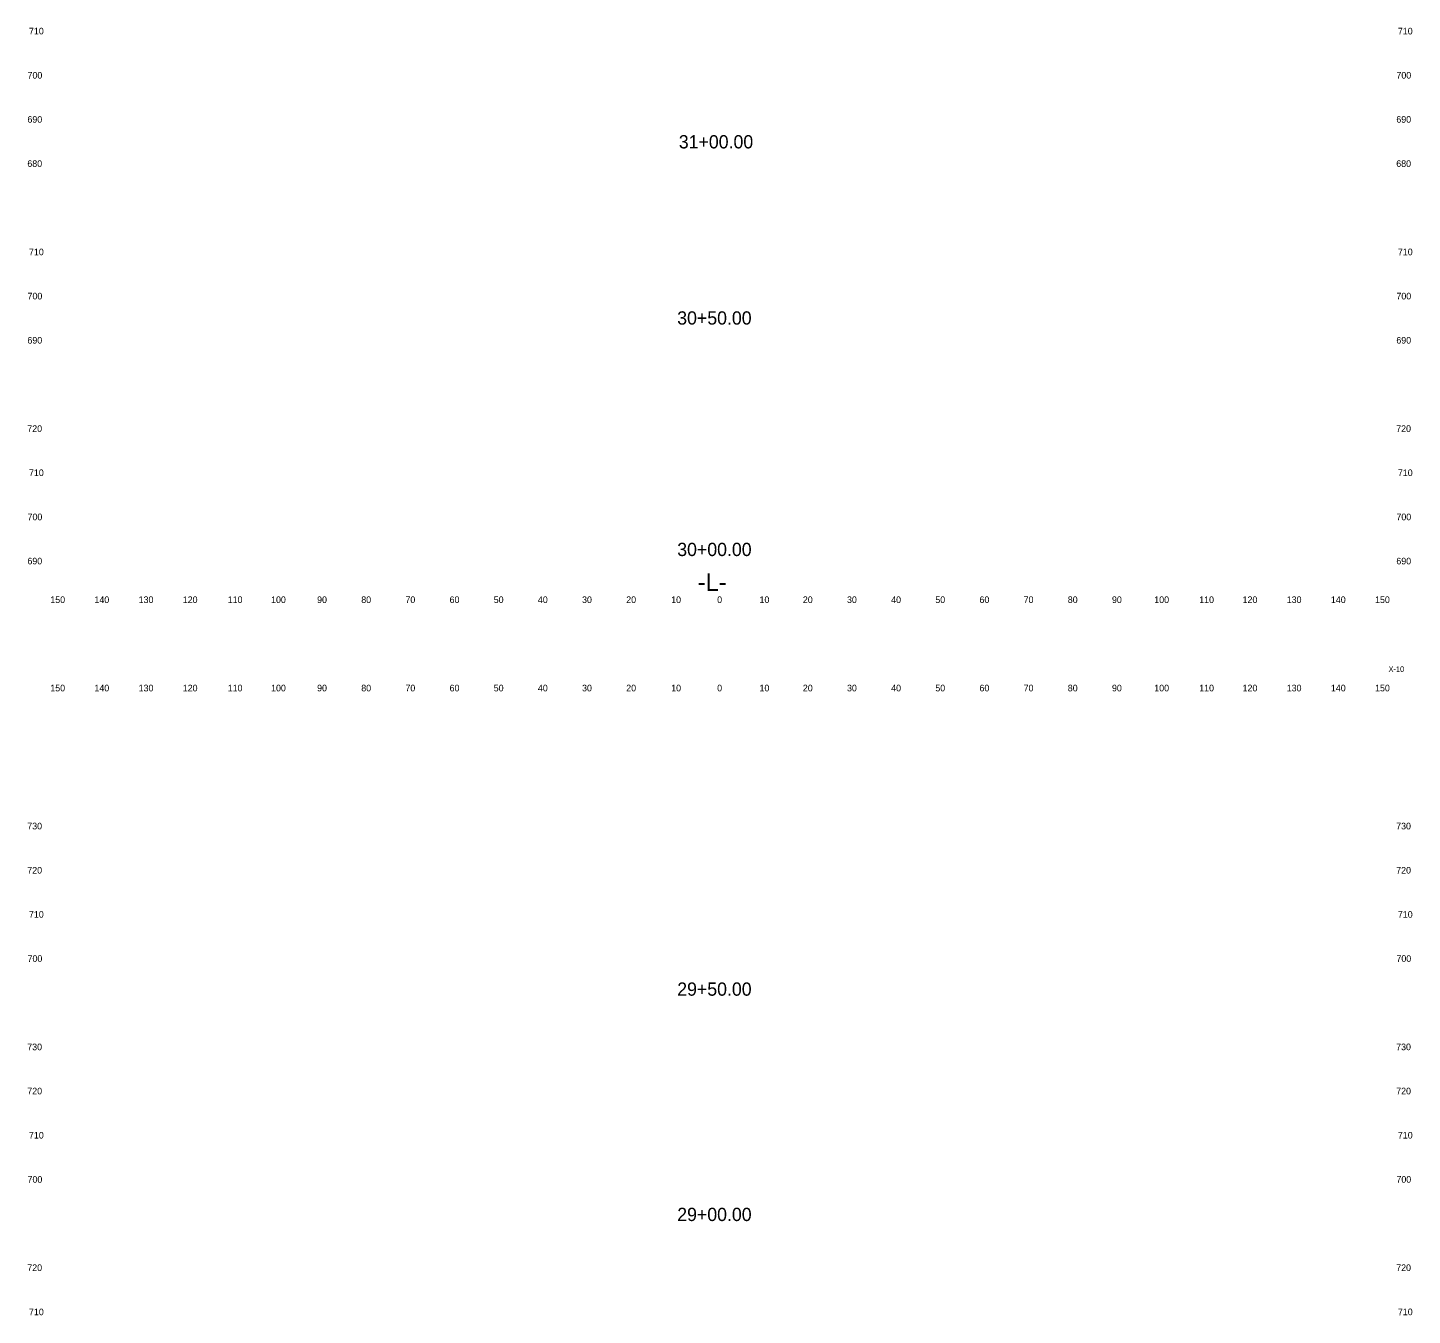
# Model space of a CAD drawing. Extents: x 3 to 317, y 0 to 2407.
# Drawn here: x 3.3 to 316.9, y 1820 to 2111.5 of the extents above; entities that cross this region are included whole.
import ezdxf

# ---------------------------------------------------------------- set-up
doc = ezdxf.new("R2010")
doc.units = 0
for name, color, linetype in [('Prop XS Ditch Standard Text', 7, 'Continuous'), ('Prop XS Dump Level', 7, 'Continuous'), ('Prop XS SE Text', 7, 'Continuous'), ('Prop XS Sheet Number', 7, 'Continuous'), ('Prop XS SS Elevation Text', 7, 'Continuous')]:
    doc.layers.add(name, color=color, linetype=linetype)

msp = doc.modelspace()

# ---------------------------------------------------------------- texts
at = {"layer": 'Prop XS Ditch Standard Text'}
for s, p in [('31+00.00', (150.77, 2084.19)), ('30+50.00', (150.41, 2044.3)), ('30+00.00', (150.41, 1991.89)), ('29+50.00', (150.41, 1892.34)), ('29+00.00', (150.41, 1841.32))]:
    msp.add_text(s, height=3, dxfattribs=at).set_placement(p)
at = {"layer": 'Prop XS Dump Level'}
for s, p in [('150', (8.44, 1981.25)), ('140', (18.44, 1981.25)), ('130', (28.44, 1981.25)), ('120', (38.44, 1981.25)), ('110', (48.62, 1981.25)), ('100', (58.44, 1981.25)), ('90', (68.86, 1981.25)), ('80', (78.86, 1981.25)), ('70', (88.86, 1981.25)), ('60', (98.86, 1981.25)), ('50', (108.86, 1981.25)), ('40', (118.86, 1981.25)), ('30', (128.86, 1981.25)), ('20', (138.86, 1981.25)), ('10', (149.04, 1981.25)), ('0', (159.45, 1981.25)), ('10', (169.04, 1981.25)), ('20', (178.86, 1981.25)), ('30', (188.86, 1981.25)), ('40', (198.86, 1981.25)), ('50', (208.86, 1981.25)), ('60', (218.86, 1981.25)), ('70', (228.86, 1981.25)), ('80', (238.86, 1981.25)), ('90', (248.86, 1981.25)), ('100', (258.44, 1981.25)), ('110', (268.62, 1981.25)), ('120', (278.44, 1981.25)), ('130', (288.44, 1981.25)), ('140', (298.44, 1981.25)), ('150', (308.44, 1981.25)), ('150', (8.44, 1961.25)), ('140', (18.44, 1961.25)), ('130', (28.44, 1961.25)), ('120', (38.44, 1961.25)), ('110', (48.62, 1961.25)), ('100', (58.44, 1961.25)), ('90', (68.86, 1961.25)), ('80', (78.86, 1961.25)), ('70', (88.86, 1961.25)), ('60', (98.86, 1961.25)), ('50', (108.86, 1961.25)), ('40', (118.86, 1961.25)), ('30', (128.86, 1961.25)), ('20', (138.86, 1961.25)), ('10', (149.04, 1961.25)), ('0', (159.45, 1961.25)), ('10', (169.04, 1961.25)), ('20', (178.86, 1961.25)), ('30', (188.86, 1961.25)), ('40', (198.86, 1961.25)), ('50', (208.86, 1961.25)), ('60', (218.86, 1961.25)), ('70', (228.86, 1961.25)), ('80', (238.86, 1961.25)), ('90', (248.86, 1961.25)), ('100', (258.44, 1961.25)), ('110', (268.62, 1961.25)), ('120', (278.44, 1961.25)), ('130', (288.44, 1961.25)), ('140', (298.44, 1961.25)), ('150', (308.44, 1961.25))]:
    msp.add_text(s, height=1.5, dxfattribs=at).set_placement(p)
at = {"layer": 'Prop XS SE Text'}
for s, p in [('710', (3.61, 2110)), ('710', (313.61, 2110)), ('700', (3.28, 2100)), ('700', (313.28, 2100)), ('690', (3.26, 2090)), ('690', (313.26, 2090)), ('680', (3.24, 2080)), ('680', (313.24, 2080)), ('710', (3.61, 2060)), ('710', (313.61, 2060)), ('700', (3.28, 2050)), ('700', (313.28, 2050)), ('690', (3.26, 2040)), ('690', (313.26, 2040)), ('720', (3.23, 2020)), ('720', (313.23, 2020)), ('710', (3.61, 2010)), ('710', (313.61, 2010)), ('700', (3.28, 2000)), ('700', (313.28, 2000)), ('690', (3.26, 1990)), ('690', (313.26, 1990)), ('730', (3.22, 1930)), ('730', (313.22, 1930)), ('720', (3.23, 1920)), ('720', (313.23, 1920)), ('710', (3.61, 1910)), ('710', (313.61, 1910)), ('700', (3.28, 1900)), ('700', (313.28, 1900)), ('730', (3.22, 1880)), ('730', (313.22, 1880)), ('720', (3.23, 1870)), ('720', (313.23, 1870)), ('710', (3.61, 1860)), ('710', (313.61, 1860)), ('700', (3.28, 1850)), ('700', (313.28, 1850)), ('720', (3.23, 1830)), ('720', (313.23, 1830)), ('710', (3.61, 1820)), ('710', (313.61, 1820))]:
    msp.add_text(s, height=1.5, dxfattribs=at).set_placement(p)
at = {"layer": 'Prop XS Sheet Number'}
msp.add_text('X-10', height=1.25, dxfattribs=at).set_placement((311.5, 1965.66))
at = {"layer": 'Prop XS SS Elevation Text'}
msp.add_text('-L-', height=4, dxfattribs=at).set_placement((155.06, 1984))

doc.saveas('drawing.dxf')
